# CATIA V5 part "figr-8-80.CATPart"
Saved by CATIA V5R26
Part number: Part1
Bounding box of the stored display mesh (mm): x -52.625 to 52.625, y -77.625 to 77.625, z 0 to 30
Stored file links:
  D:\_Deepak\CATIA\CATIA V5-6R2016_Deepak\Resources\Part files\Partfiles\c08_catia_v5_6r2016_prt\figr-8-80.CATPart
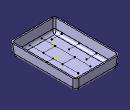
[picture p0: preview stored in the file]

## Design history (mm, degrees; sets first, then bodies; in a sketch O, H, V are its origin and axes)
Set1
  Plane1: type Offset, RefPlane xy-plane, Offset 30
  Plane2: type Offset, RefPlane face of Pad1, Offset -8, reversed
Body1 (main body)
  Sketch1 on xy-plane, origin (0, 0, 0), H (1, 0, 0), V (0, 1, 0)
    line L1 (-50, 75) -> (50, 75)
    line L2 (50, 75) -> (50, -75)
    line L3 (50, -75) -> (-50, -75)
    line L4 (-50, -75) -> (-50, 75)
    axis line L5 (50, -75) -> (-50, 75)
    length L3 = 100
    length L2 = 150
    horizontal: L1 H, L3 H
    vertical: L2 V, L4 V
    midpoint: O L5
  Pad1: profile Sketch1, direction (0, 0, 1), length 0, opposite side up to Plane1
  Draft1: Angle -5, Neutral face of Pad1, PullDir face of Pad1, SupportToDraft (face of Pad1; face of Pad1; face of Pad1; face of Pad1)
  Fillet1: radius 7, on edge [face of Pad1 | face of Pad1] (x4)
  Fillet2: radius 10, on edge [face of Pad1 | face of Pad1] (x4)
  Shell1: ExtOffset 0, Face face of Pad1, IntOffset 3
  Sketch2 on Plane2, origin (0, 0, 22), H (1, 0, 0), V (0, -1, 0)
    line L1 (28.1747, 54.0191) -> (28.1747, -59.2866)
    line L2 (0, 54.0191) -> (0, -59.2866)
    point P3 (0, 54.0191)
    line L3 (-9.5939, 0) -> (-33.0562, 0)
    point P5 (-9.5939, 0)
    line L4 (-9.5939, -40.4023) -> (-33.0562, -40.4023)
    point P7 (-9.5939, -40.4023)
    point P8 (-33.0562, -40.4023)
    point P9 (-33.0562, 40.4023)
    point P10 (-9.5939, 40.4023)
    line L5 (-9.5939, 40.4023) -> (-33.0562, 40.4023)
    line L6 (28.1747, 22.6983) -> (0, 22.6983)
    point P11 (28.1747, 22.6983)
    point P12 (0, 22.6983)
    point P13 (0, -22.6983)
    point P14 (28.1747, -22.6983)
    line L7 (28.1747, -22.6983) -> (0, -22.6983)
    line L8 (28.1747, 0) -> (41.8849, 0)
    point P15 (28.1747, 0)
    vertical: L1 V, L2 V
    coincidence: P3 V, P5 H, P11 L1, P12 L2, P15 L1, P15 H
    horizontal: L3 H, L4 H, L6 H, L8 H
    symmetry: P8 P9 L3, P7 P10 L3, L4 L5 L3, P12 P13 H, P11 P14 H, L6 L7 H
